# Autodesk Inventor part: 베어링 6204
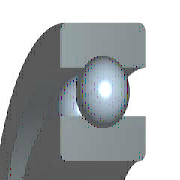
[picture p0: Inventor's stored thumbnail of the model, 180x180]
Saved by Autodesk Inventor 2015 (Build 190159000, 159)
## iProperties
Created: 2012-02
Part Number: 베어링 6204
Material: 강철, 연강
Description: 깊은 그루브 볼 베어링
Document SubType Name: Modeling
Standard: KS B 2023
Designer: mduedu
Standards Organization: KS
Language: ko-KR
Size Designation: 6204 - 20 x 47 x 14
Categories: <MemberInstance><Categories><Category DisplayName="샤프트 부품" InternalName="7f7aeb1f-a693-4053-b835-cee3144e0d98" Mnemonic="SHFT"><Category DisplayName="베어링" Inter
Density: 1 g/cm^3
Appearance: 노란색
IsCustomPart: 1
Author: mduedu
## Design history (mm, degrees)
sketch "스케치" dims "d0" = 7.02 (= -0.26 x WD + 0.26 x BD)
  geometry: L1 (3.49, 16.75)-(10.51, 16.75); L2 (7, 16.75)-(7, 13.24); L3 (7, 16.75)-(7, 20.26); L4 (4.392, 14.401)-(0, 14.401); L5 (0, 10)-(14, 10); L6 (4.392, 19.099)-(0, 19.099); L7 (0, 23.5)-(14, 23.5); L8 (14, 10)-(14, 14.401); L9 (9.608, 14.401)-(14, 14.401); L10 (9.608, 19.099)-(14, 19.099); L11 (14, 23.5)-(14, 19.099); L12 (-1.4, 0)-(8.4, 0) reference; L13 (0, -0.3)-(0, 5.3) reference
  constraints: 22 end point, 4 point on line, 2 collinear, 2 perpendicular, 2 symmetric about line, 1 midpoint, 1 parallel, 14 other
  dimensions: "d9" = 20 diameter of L5 L12 (= WD); "d11" = 47 diameter of L7 L12 (= BD); "d12" = 14 distance between parallel lines of L8 L13 (= KB); "d13" = 28.802 diameter of L9 L12 (= 0.326 x BD + 0.674 x WD)
revolve "본체" stored, may be unused: angle "d6" = 90 deg
revolve "볼" stored, may be unused: angle "d7" = 90 deg
pattern_circular "IDS_ARRAYBALL[SIMPL:T]" dims angle "d3" = 360 deg
body "Solid1"
fillet "모깎기1" dims "d1" = 1 (= KRS)
other parameters: "WD" = 20 [user parameter; used in 5 equation terms], "BD" = 47 [user parameter; used in 5 equation terms], "KB" = 14 [user parameter; used in 1 equation term], "KRS" = 1 [user parameter; used in 1 equation term], "d4" = 0, "d5" = 0, "d8" = 0, "d14" = 0, "d15" = 0, "BBA" = 0 [user parameter], "BC0" = 6550000 [user parameter], "BC" = 1.27e+07 [user parameter], "BR" = 23.5 (= 0.5 x BD) [user parameter]
